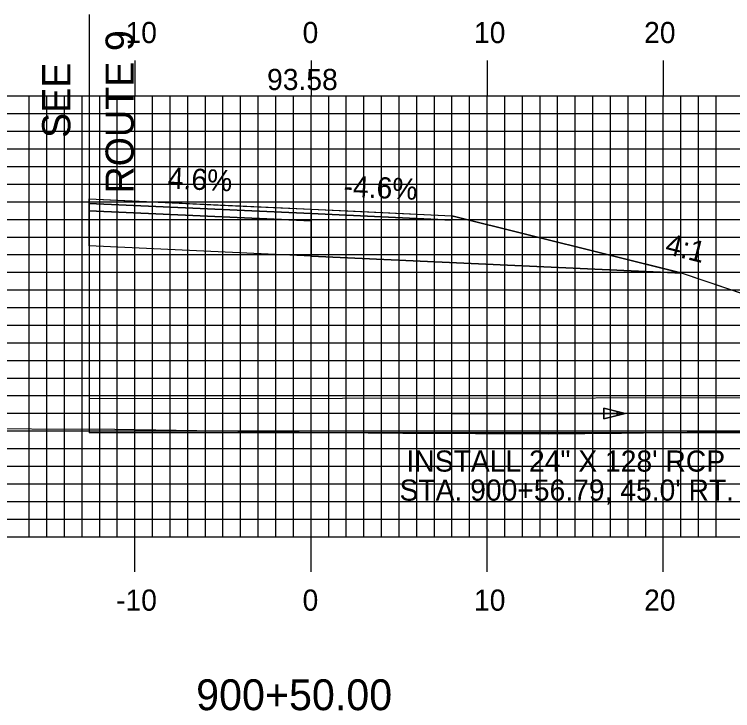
# Model space of a CAD drawing. Extents: x 856323 to 856666, y 364765 to 364985.
# Drawn here: x 856471.92 to 856512.7, y 364818.43 to 364857.93 of the extents above; entities that cross this region are included whole.
import ezdxf

# ---------------------------------------------------------------- set-up
doc = ezdxf.new("R2010")
doc.units = 0
for name, color, linetype in [('ANNOTATION', 7, 'Continuous'), ('D_Drainage_Culvert', 7, 'Continuous'), ('D_Roadway_Centerline', 7, 'Continuous'), ('D_Roadway_Centerline_Text', 7, 'Continuous'), ('D_Roadway_Edge_Shoulder', 7, 'Continuous'), ('D_Roadway_Edge_TW', 7, 'Continuous'), ('D_Roadway_FinishedGrade', 7, 'Continuous'), ('D_Roadway_Pavement', 7, 'Continuous'), ('D_Roadway_SlopeLines', 7, 'Continuous'), ('D_Roadway_SubGrade', 7, 'Continuous'), ('D_Text_Standard', 7, 'Continuous'), ('H_V ANNOTATION', 7, 'Continuous'), ('MAJOR', 7, 'Continuous'), ('MINOR', 7, 'Continuous'), ('S_Roadway_Centerline', 7, 'Continuous')]:
    doc.layers.add(name, color=color, linetype=linetype)

msp = doc.modelspace()

# ---------------------------------------------------------------- linework, layer by layer
at = {"layer": 'D_Drainage_Culvert'}
msp.add_line((856533.694, 364834.192), (856476.17, 364834.192), dxfattribs=at)
msp.add_lwpolyline([(856533.694, 364834.192), (856533.691, 364836.192), (856476.17, 364836.121)], dxfattribs=at)
at = {"layer": 'D_Roadway_Centerline'}
msp.add_lwpolyline([(856476.17, 364847.458), (856483.623, 364847.116), (856488.768, 364846.88), (856491.27, 364846.765), (856496.768, 364846.512), (856500.528, 364845.572), (856508.768, 364843.512), (856509.507, 364843.328), (856509.84, 364843.244), (856518.287, 364840.401), (856528.903, 364836.827)], dxfattribs=at)
at = {"layer": 'D_Roadway_Edge_Shoulder'}
msp.add_lwpolyline([(856488.768, 364846.88), (856496.768, 364846.512), (856496.768, 364846.262), (856488.768, 364846.63)], close=True, dxfattribs=at)
at = {"layer": 'D_Roadway_Edge_TW'}
msp.add_lwpolyline([(856476.17, 364847.458), (856488.768, 364846.88), (856488.768, 364846.63), (856476.17, 364847.208)], close=True, dxfattribs=at)
msp.add_lwpolyline([(856476.17, 364847.458), (856488.768, 364846.88), (856488.768, 364846.63), (856476.17, 364847.208)], close=True, dxfattribs=at)
msp.add_lwpolyline([(856476.17, 364847.458), (856488.768, 364846.88), (856488.768, 364846.63), (856476.17, 364847.208)], close=True, dxfattribs=at)
msp.add_lwpolyline([(856476.17, 364847.458), (856476.17, 364847.208)], dxfattribs=at)
msp.add_lwpolyline([(856476.17, 364847.458), (856476.17, 364847.208)], dxfattribs=at)
at = {"layer": 'D_Roadway_FinishedGrade'}
for p, q in [((856505.399, 364835.593), (856505.399, 364835.293)), ((856506.147, 364835.406), (856505.399, 364835.593)), ((856496.791, 364835.293), (856506.599, 364835.293)), ((856505.399, 364835.293), (856506.147, 364835.293)), ((856506.147, 364835.293), (856505.399, 364835.293)), ((856505.399, 364835.293), (856505.399, 364834.993)), ((856505.399, 364834.993), (856506.147, 364835.18)), ((856506.147, 364835.293), (856506.147, 364835.406)), ((856506.599, 364835.293), (856506.147, 364835.406)), ((856506.147, 364835.406), (856506.147, 364835.293)), ((856506.147, 364835.293), (856506.599, 364835.293)), ((856506.599, 364835.293), (856506.147, 364835.293)), ((856506.147, 364835.293), (856506.147, 364835.18)), ((856506.147, 364835.18), (856506.599, 364835.293)), ((856506.147, 364835.18), (856506.147, 364835.293))]:
    msp.add_line(p, q, dxfattribs=at)
msp.add_lwpolyline([(856505.399, 364835.593), (856506.599, 364835.293), (856505.399, 364834.993)], close=True, dxfattribs=at)
at = {"layer": 'D_Roadway_Pavement'}
msp.add_lwpolyline([(856476.17, 364847.208), (856488.768, 364846.63), (856488.768, 364846.214), (856476.17, 364846.792)], close=True, dxfattribs=at)
msp.add_lwpolyline([(856476.17, 364847.208), (856488.768, 364846.63), (856488.768, 364846.214), (856476.17, 364846.792)], close=True, dxfattribs=at)
msp.add_lwpolyline([(856476.17, 364847.208), (856488.768, 364846.63), (856488.768, 364846.214), (856476.17, 364846.792)], close=True, dxfattribs=at)
msp.add_lwpolyline([(856476.17, 364847.208), (856488.768, 364846.63), (856488.768, 364846.214), (856476.17, 364846.792)], close=True, dxfattribs=at)
for points in [[(856476.17, 364847.208), (856476.17, 364846.792)], [(856476.17, 364847.208), (856476.17, 364846.792)], [(856476.17, 364847.208), (856476.17, 364846.792)], [(856476.17, 364847.208), (856476.17, 364846.792)], [(856488.768, 364846.63), (856488.768, 364846.214)], [(856488.768, 364846.63), (856488.768, 364846.214)], [(856488.768, 364846.63), (856488.768, 364846.214)], [(856488.768, 364846.63), (856488.768, 364846.214)], [(856488.768, 364846.63), (856488.768, 364846.214)], [(856488.768, 364846.63), (856488.768, 364846.214)], [(856488.768, 364846.63), (856488.768, 364846.214)], [(856488.768, 364846.63), (856488.768, 364846.214)]]:
    msp.add_lwpolyline(points, dxfattribs=at)
at = {"layer": 'D_Roadway_SlopeLines'}
msp.add_lwpolyline([(856496.768, 364846.512), (856509.84, 364843.244), (856528.902, 364836.827)], dxfattribs=at)
at = {"layer": 'D_Roadway_SubGrade'}
for p, q in [((856476.17, 364857.932), (856476.17, 364844.792)), ((856476.17, 364844.792), (856476.17, 364834.192))]:
    msp.add_line(p, q, dxfattribs=at)
for points in [[(856476.17, 364846.792), (856488.768, 364846.214), (856488.768, 364844.214), (856476.17, 364844.792)], [(856476.17, 364846.792), (856488.768, 364846.214), (856488.768, 364844.214), (856476.17, 364844.792)], [(856488.768, 364846.214), (856488.768, 364846.63), (856496.768, 364846.262), (856496.768, 364846.512), (856509.84, 364843.244), (856488.768, 364844.214)], [(856488.768, 364844.214), (856509.84, 364843.244), (856496.768, 364846.512), (856496.768, 364846.262), (856488.768, 364846.63), (856488.768, 364846.214)], [(856488.768, 364846.214), (856488.768, 364846.63), (856496.768, 364846.262), (856496.768, 364846.512), (856509.84, 364843.244), (856488.768, 364844.214)]]:
    msp.add_lwpolyline(points, close=True, dxfattribs=at)
msp.add_lwpolyline([(856476.17, 364846.792), (856476.17, 364844.792)], dxfattribs=at)
msp.add_lwpolyline([(856476.17, 364846.792), (856476.17, 364844.792)], dxfattribs=at)
at = {"layer": 'MAJOR'}
for p, q in [((856478.768, 364855.306), (856478.768, 364853.302)), ((856488.768, 364855.306), (856488.768, 364853.302)), ((856498.768, 364855.306), (856498.768, 364853.302)), ((856508.768, 364855.306), (856508.768, 364853.302)), ((856348.768, 364853.302), (856628.768, 364853.302)), ((856348.768, 364853.302), (856628.768, 364853.302)), ((856478.768, 364828.302), (856478.768, 364853.302)), ((856488.768, 364828.302), (856488.768, 364853.302)), ((856498.768, 364828.302), (856498.768, 364853.302)), ((856508.768, 364828.302), (856508.768, 364853.302)), ((856348.768, 364848.302), (856628.768, 364848.302)), ((856348.768, 364843.302), (856628.768, 364843.302)), ((856348.768, 364838.302), (856628.768, 364838.302)), ((856348.768, 364833.302), (856628.768, 364833.302)), ((856348.768, 364828.302), (856628.768, 364828.302)), ((856348.768, 364828.302), (856628.768, 364828.302)), ((856478.768, 364826.298), (856478.768, 364828.302)), ((856488.768, 364826.298), (856488.768, 364828.302)), ((856498.768, 364826.298), (856498.768, 364828.302)), ((856508.768, 364826.298), (856508.768, 364828.302))]:
    msp.add_line(p, q, dxfattribs=at)
at = {"layer": 'MINOR'}
for p, q in [((856472.768, 364828.302), (856472.768, 364853.302)), ((856473.768, 364828.302), (856473.768, 364853.302)), ((856474.768, 364828.302), (856474.768, 364853.302)), ((856475.768, 364828.302), (856475.768, 364853.302)), ((856476.768, 364828.302), (856476.768, 364853.302)), ((856477.768, 364828.302), (856477.768, 364853.302)), ((856479.768, 364828.302), (856479.768, 364853.302)), ((856480.768, 364828.302), (856480.768, 364853.302)), ((856481.768, 364828.302), (856481.768, 364853.302)), ((856482.768, 364828.302), (856482.768, 364853.302)), ((856483.768, 364828.302), (856483.768, 364853.302)), ((856484.768, 364828.302), (856484.768, 364853.302)), ((856485.768, 364828.302), (856485.768, 364853.302)), ((856486.768, 364828.302), (856486.768, 364853.302)), ((856487.768, 364828.302), (856487.768, 364853.302)), ((856489.768, 364828.302), (856489.768, 364853.302)), ((856490.768, 364828.302), (856490.768, 364853.302)), ((856491.768, 364828.302), (856491.768, 364853.302)), ((856492.768, 364828.302), (856492.768, 364853.302)), ((856493.768, 364828.302), (856493.768, 364853.302)), ((856494.768, 364828.302), (856494.768, 364853.302)), ((856495.768, 364828.302), (856495.768, 364853.302)), ((856496.768, 364828.302), (856496.768, 364853.302)), ((856497.768, 364828.302), (856497.768, 364853.302)), ((856499.768, 364828.302), (856499.768, 364853.302)), ((856500.768, 364828.302), (856500.768, 364853.302)), ((856501.768, 364828.302), (856501.768, 364853.302)), ((856502.768, 364828.302), (856502.768, 364853.302)), ((856503.768, 364828.302), (856503.768, 364853.302)), ((856504.768, 364828.302), (856504.768, 364853.302)), ((856505.768, 364828.302), (856505.768, 364853.302)), ((856506.768, 364828.302), (856506.768, 364853.302)), ((856507.768, 364828.302), (856507.768, 364853.302)), ((856509.768, 364828.302), (856509.768, 364853.302)), ((856510.768, 364828.302), (856510.768, 364853.302)), ((856511.768, 364828.302), (856511.768, 364853.302)), ((856348.768, 364852.302), (856628.768, 364852.302)), ((856348.768, 364851.302), (856628.768, 364851.302)), ((856348.768, 364850.302), (856628.768, 364850.302)), ((856348.768, 364849.302), (856628.768, 364849.302)), ((856348.768, 364847.302), (856628.768, 364847.302)), ((856348.768, 364846.302), (856628.768, 364846.302)), ((856348.768, 364845.302), (856628.768, 364845.302)), ((856348.768, 364844.302), (856628.768, 364844.302)), ((856348.768, 364842.302), (856628.768, 364842.302)), ((856348.768, 364841.302), (856628.768, 364841.302)), ((856348.768, 364840.302), (856628.768, 364840.302)), ((856348.768, 364839.302), (856628.768, 364839.302)), ((856348.768, 364837.302), (856628.768, 364837.302)), ((856348.768, 364836.302), (856628.768, 364836.302)), ((856348.768, 364835.302), (856628.768, 364835.302)), ((856348.768, 364834.302), (856628.768, 364834.302)), ((856348.768, 364832.302), (856628.768, 364832.302)), ((856348.768, 364831.302), (856628.768, 364831.302)), ((856348.768, 364830.302), (856628.768, 364830.302)), ((856348.768, 364829.302), (856628.768, 364829.302))]:
    msp.add_line(p, q, dxfattribs=at)
at = {"layer": 'S_Roadway_Centerline'}
msp.add_lwpolyline([(856468.17, 364834.44), (856477.631, 364834.392), (856488.091, 364834.229), (856493.984, 364834.166), (856502.233, 364834.138), (856506.394, 364834.174), (856523.832, 364834.442), (856525.471, 364834.453), (856525.841, 364834.454), (856526.497, 364834.44), (856538.058, 364834.187), (856544.846, 364834.073), (856550.24, 364834.018), (856559.769, 364833.685), (856562.105, 364833.634), (856563.443, 364833.597), (856571.424, 364833.699)], dxfattribs=at)

# ---------------------------------------------------------------- texts
at = {"layer": 'ANNOTATION'}
for s, height, rotation, p in [('ROUTE 9', 1.6, 90, (856478.701, 364847.765)), ('SEE', 1.6, 90, (856475.101, 364850.914)), ('4.6%', 1.2, 357.3725, (856480.615, 364848.057)), ('-4.6%', 1.2, 357.3663, (856490.594, 364847.598)), ('4:1', 1.2, 345.9638, (856508.81, 364844.363))]:
    msp.add_text(s, height=height, rotation=rotation, dxfattribs=at).set_placement(p)
at = {"layer": 'D_Roadway_Centerline_Text'}
for s, p in [('93.58', (856486.269, 364853.639)), ('INSTALL 24" X 128\' RCP', (856494.185, 364831.992))]:
    msp.add_text(s, height=1.2, dxfattribs=at).set_placement(p)
at = {"layer": 'D_Text_Standard'}
msp.add_text("STA. 900+56.79, 45.0' RT.", height=1.2, dxfattribs=at).set_placement((856493.79, 364830.344))
at = {"layer": 'H_V ANNOTATION'}
for s, height, p in [('-10', 1.2, (856477.698, 364856.302)), ('0', 1.2, (856488.287, 364856.302)), ('10', 1.2, (856498.019, 364856.302)), ('20', 1.2, (856507.676, 364856.302)), ('-10', 1.2, (856477.698, 364824.102)), ('0', 1.2, (856488.287, 364824.102)), ('10', 1.2, (856498.019, 364824.102)), ('20', 1.2, (856507.676, 364824.102)), ('900+50.00', 1.75, (856482.245, 364818.458))]:
    msp.add_text(s, height=height, dxfattribs=at).set_placement(p)

doc.saveas('drawing.dxf')
